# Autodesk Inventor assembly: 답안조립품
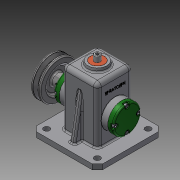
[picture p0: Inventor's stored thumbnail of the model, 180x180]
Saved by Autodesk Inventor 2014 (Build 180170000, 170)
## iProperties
Created: 2016-02
Part Number: 답안조립품
Document SubType Name: Assembly
Designer: D.Y.KIM
Author: D.Y.KIM
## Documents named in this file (16)
- C:\Users\Administrator\Desktop\460211V1029\답안조립품.iam
- C:\Users\Administrator\Desktop\460211V1029\1-본체.ipt
- C:\Users\Administrator\Desktop\460211V1029\뒤커버.ipt
- C:\Users\Administrator\Desktop\460211V1029\앞커버.ipt
- C:\Users\Administrator\Desktop\460211V1029\베어링 12 x 32 x 10.ipt
- C:\Users\Administrator\Desktop\460211V1029\편심축.ipt
- C:\Users\Administrator\Desktop\460211V1029\오일실 12 25 7.ipt
- C:\Users\Administrator\Desktop\460211V1029\키 4 x 4 x 10.ipt
- C:\Users\Administrator\Desktop\460211V1029\링크.ipt
- C:\Users\Administrator\Desktop\460211V1029\핀 5 x 18.ipt
- C:\Users\Administrator\Desktop\460211V1029\슬라이드.ipt
- C:\Users\Administrator\Desktop\460211V1029\부시.ipt
- C:\Users\Administrator\Desktop\460211V1029\V벨트풀리.ipt
- C:\Users\Administrator\Desktop\460211V1029\멈춤나사 M3x8.ipt
- C:\Users\Administrator\Desktop\460211V1029\볼트 M4 x 12.ipt
- C:\Users\Administrator\Desktop\460211V1029\고정핀 1.2 x 10.ipt
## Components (12 placed, 5 different names)
1. 1-본체:1 — 각도:1, 각도:2, 각도:3
2. 핀 5 x 18:1 — 각도:4, 플러쉬:4
3. V벨트풀리:1 — 플러쉬:2
4. 고정핀 1.2 x 10:1 — 플러쉬:3
5. ISO 4762 M4 x 12:1 — 각도:3
6. ISO 4762 M4 x 12:3
7. ISO 4762 M4 x 12:4
8. ISO 4762 M4 x 12:5
9. ISO 4762 M4 x 12:2 — 각도:2
10. ISO 4762 M4 x 12:6
11. ISO 4762 M4 x 12:7
12. ISO 4762 M4 x 12:8
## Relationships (7: Angle 4, Flush 3)
- 플러쉬:2 [Flush]: V벨트풀리:1
- 각도:1 [Angle]: 1-본체:1
- 각도:2 [Angle]: 1-본체:1 ↔ ISO 4762 M4 x 12:2
- 각도:3 [Angle]: 1-본체:1 ↔ ISO 4762 M4 x 12:1
- 각도:4 [Angle]: 핀 5 x 18:1
- 플러쉬:3 [Flush]: 고정핀 1.2 x 10:1
- 플러쉬:4 [Flush]: 핀 5 x 18:1
